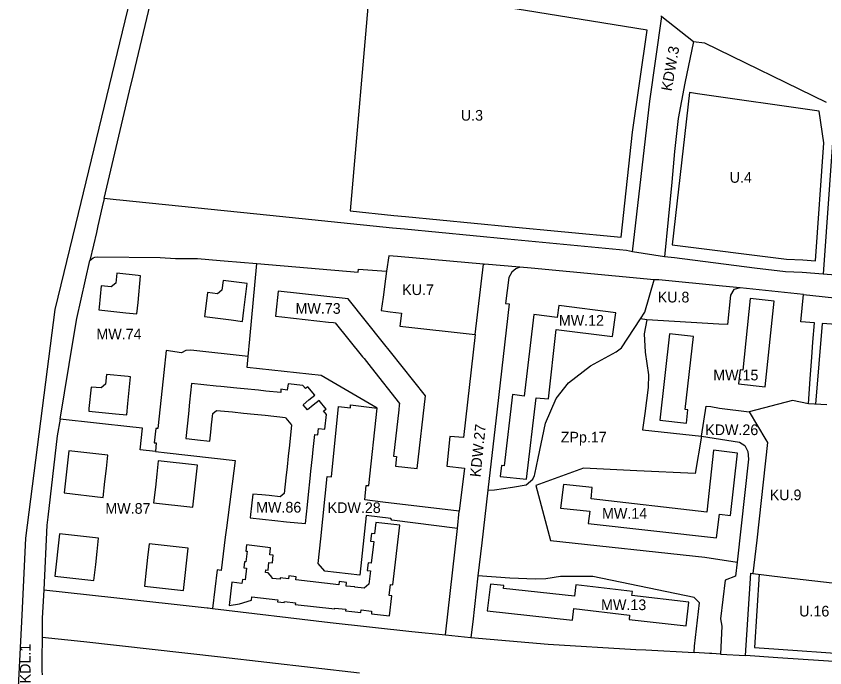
# Model space of a CAD drawing. Extents: x 7424434 to 7425898, y 5541432 to 5542659.
# Drawn here: x 7424614.7 to 7424993.9, y 5541854.6 to 5542160 of the extents above; entities that cross this region are included whole.
import ezdxf

# ---------------------------------------------------------------- set-up
doc = ezdxf.new("R2010")
doc.units = 0
for name, color, linetype in [('linie rozgraniczające', 7, 'Continuous'), ('nieprzekraczalne linie zabudowy', 7, 'Continuous'), ('obowiazujace linie zabudowy', 7, 'Continuous'), ('przeznaczenia terenów', 7, 'Continuous')]:
    doc.layers.add(name, color=color, linetype=linetype)

msp = doc.modelspace()

# ---------------------------------------------------------------- linework, layer by layer
at = {"layer": 'linie rozgraniczające'}
for p, q in [((7424665.78, 5542157.87), (7424709.76, 5542339.63)), ((7424674.48, 5542152.32), (7424683.68, 5542191.73)), ((7424911.87, 5542120.2), (7424917.55, 5542159.83)), ((7424917.08, 5542160.2), (7424917.55, 5542159.83)), ((7424917.55, 5542159.83), (7424932.4, 5542148.13)), ((7424642.66, 5542062.32), (7424665.78, 5542157.87)), ((7424669.75, 5542132.74), (7424674.48, 5542152.32)), ((7424932.4, 5542148.13), (7424928.28, 5542128.55)), ((7424932.4, 5542148.13), (7424937.56, 5542147.46)), ((7424937.56, 5542147.46), (7424994.63, 5542119.66)), ((7424667.94, 5542125.06), (7424669.75, 5542132.74)), ((7424928.28, 5542128.55), (7424925.24, 5542112.08)), ((7424656.01, 5542074.49), (7424667.94, 5542125.06)), ((7424903.7, 5542049.58), (7424911.87, 5542120.2)), ((7424925.24, 5542112.08), (7424923.48, 5542096.58)), ((7424997.54, 5542100.77), (7424993.13, 5542039.11)), ((7424923.48, 5542096.58), (7424922.23, 5542082.23)), ((7424922.23, 5542082.23), (7424918.72, 5542047.27)), ((7424656.01, 5542074.49), (7424655.09, 5542070.61)), ((7424661.58, 5542073.91), (7424656.01, 5542074.49)), ((7424661.62, 5542073.91), (7424661.58, 5542073.91)), ((7424663.37, 5542073.73), (7424661.62, 5542073.91)), ((7424733.65, 5542066.56), (7424663.37, 5542073.73)), ((7424655.09, 5542070.61), (7424653.05, 5542061.69)), ((7424791.18, 5542060.69), (7424733.65, 5542066.56)), ((7424633.04, 5542022.53), (7424642.66, 5542062.32)), ((7424653.05, 5542061.69), (7424652.36, 5542058.67)), ((7424652.36, 5542058.67), (7424650.99, 5542052.64)), ((7424796.79, 5542060.12), (7424791.18, 5542060.69)), ((7424845.09, 5542055.47), (7424796.79, 5542060.12)), ((7424901.01, 5542050.11), (7424845.09, 5542055.47)), ((7424650.99, 5542052.64), (7424649.32, 5542045.47)), ((7424903.7, 5542049.58), (7424901.01, 5542050.11)), ((7424918.72, 5542047.27), (7424903.7, 5542049.58)), ((7424649.32, 5542045.47), (7424650.81, 5542046.77)), ((7424650.81, 5542046.77), (7424651.6, 5542047.07)), ((7424651.6, 5542047.07), (7424653.06, 5542047.28)), ((7424653.06, 5542047.28), (7424682.27, 5542046.94)), ((7424682.27, 5542046.94), (7424689.5, 5542046.5)), ((7424689.5, 5542046.5), (7424697.61, 5542046.41)), ((7424697.61, 5542046.41), (7424699.77, 5542046.44)), ((7424699.77, 5542046.44), (7424710.35, 5542045.47)), ((7424789.43, 5542047.72), (7424788.46, 5542040.46)), ((7424793.49, 5542047.36), (7424789.43, 5542047.72)), ((7424833.85, 5542043.8), (7424793.49, 5542047.36)), ((7424923.5, 5542046.67), (7424918.72, 5542047.27)), ((7424961.02, 5542041.95), (7424923.5, 5542046.67)), ((7424643.14, 5542018.33), (7424649.32, 5542045.47)), ((7424710.35, 5542045.47), (7424712.29, 5542045.35)), ((7424712.29, 5542045.35), (7424727.53, 5542044.01)), ((7424724.3, 5542008.68), (7424727.53, 5542044.01)), ((7424727.53, 5542044.01), (7424775.07, 5542039.96)), ((7424830.04, 5542010.78), (7424833.85, 5542043.8)), ((7424833.85, 5542043.8), (7424834.39, 5542043.75)), ((7424850.93, 5542042.31), (7424834.39, 5542043.75)), ((7424850.93, 5542042.31), (7424849.03, 5542041.57)), ((7424856.18, 5542041.89), (7424850.93, 5542042.31)), ((7424975.49, 5542040.15), (7424961.02, 5542041.95)), ((7424775.07, 5542039.96), (7424775.24, 5542041.46)), ((7424775.24, 5542041.46), (7424788.46, 5542040.46)), ((7424788.46, 5542040.46), (7424787.97, 5542036.88)), ((7424847.12, 5542040.01), (7424845.69, 5542037.54)), ((7424849.03, 5542041.57), (7424847.12, 5542040.01)), ((7424913.95, 5542036.5), (7424856.18, 5542041.89)), ((7424983.28, 5542039.88), (7424975.49, 5542040.15)), ((7424993.13, 5542039.11), (7424983.28, 5542039.88)), ((7425012.26, 5542037.62), (7424993.13, 5542039.11)), ((7424787.97, 5542036.88), (7424786.83, 5542028.37)), ((7424845.69, 5542037.54), (7424844.24, 5542025.38)), ((7424909.5, 5542021.32), (7424913.95, 5542036.5)), ((7424916.07, 5542036.36), (7424913.95, 5542036.5)), ((7424945.93, 5542033.43), (7424916.07, 5542036.36)), ((7424954.19, 5542032.62), (7424945.93, 5542033.43)), ((7424951.24, 5542031.86), (7424949.75, 5542029.28)), ((7424954.19, 5542032.62), (7424951.24, 5542031.86)), ((7424984.02, 5542029.59), (7424954.19, 5542032.62)), ((7424786.83, 5542028.37), (7424785.95, 5542022.03)), ((7424949.75, 5542029.28), (7424948.38, 5542015.44)), ((7424982.62, 5542016.75), (7424984.02, 5542029.59)), ((7424984.02, 5542029.59), (7425010.84, 5542026.55)), ((7424845.92, 5542025.19), (7424840.27, 5541975.86)), ((7424844.24, 5542025.38), (7424845.92, 5542025.19)), ((7424628.68, 5541988.49), (7424633.04, 5542022.53)), ((7424785.95, 5542022.03), (7424790.07, 5542021.46)), ((7424790.07, 5542021.46), (7424795.4, 5542020.77)), ((7424795.4, 5542020.77), (7424794.71, 5542014.7)), ((7424907.57, 5542018.17), (7424909.5, 5542021.32)), ((7424641.62, 5542009.11), (7424643.14, 5542018.33)), ((7424898.57, 5542004.58), (7424907.57, 5542018.17)), ((7424910.51, 5542017.75), (7424907.57, 5542018.17)), ((7424910.51, 5542017.75), (7424909.3, 5542011.06)), ((7424944.31, 5542015.69), (7424910.51, 5542017.75)), ((7424948.38, 5542015.44), (7424944.31, 5542015.69)), ((7424989.06, 5542016.28), (7424982.62, 5542016.75)), ((7424988.4, 5542007.18), (7424989.06, 5542016.28)), ((7424794.71, 5542014.7), (7424830.04, 5542010.78)), ((7424635.31, 5541971.16), (7424641.62, 5542009.11)), ((7424723.55, 5542000.52), (7424724.3, 5542008.68)), ((7424830.04, 5542010.78), (7424824.47, 5541962.45)), ((7424909.3, 5542011.06), (7424909.68, 5542002.55)), ((7424896.15, 5542002.69), (7424898.57, 5542004.58)), ((7424987.89, 5542000.14), (7424988.4, 5542007.18)), ((7424685.01, 5542003.34), (7424683.95, 5541993.04)), ((7424692.24, 5542002.21), (7424685.01, 5542003.34)), ((7424694.31, 5542003.28), (7424692.24, 5542002.21)), ((7424696.64, 5542003.45), (7424694.31, 5542003.28)), ((7424723.55, 5542000.52), (7424696.64, 5542003.45)), ((7424723.07, 5541995.34), (7424723.55, 5542000.52)), ((7424884.08, 5541996.04), (7424896.15, 5542002.69)), ((7424909.68, 5542002.55), (7424911.22, 5541991.96)), ((7424987.15, 5541989.97), (7424987.89, 5542000.14)), ((7424683.95, 5541993.04), (7424681.32, 5541968.12)), ((7424757.8, 5541991.59), (7424723.07, 5541995.34)), ((7424873.7, 5541988.1), (7424884.08, 5541996.04)), ((7424783.97, 5541976.29), (7424757.8, 5541991.59)), ((7424911.22, 5541991.96), (7424911.08, 5541985.97)), ((7424986.31, 5541978.38), (7424987.15, 5541989.97)), ((7424619.31, 5541915.32), (7424628.68, 5541988.49)), ((7424867.96, 5541980.76), (7424873.7, 5541988.1)), ((7424911.08, 5541985.97), (7424909.51, 5541973.82)), ((7424771.47, 5541976.44), (7424771.47, 5541977.76)), ((7424771.47, 5541977.76), (7424783.97, 5541976.29)), ((7424862.91, 5541969.18), (7424867.96, 5541980.76)), ((7424978.75, 5541979.87), (7424958.39, 5541974.57)), ((7424986.31, 5541978.38), (7424978.75, 5541979.87)), ((7424994.88, 5541977.76), (7424986.31, 5541978.38)), ((7424762.64, 5541944.03), (7424765.96, 5541977.08)), ((7424765.96, 5541977.08), (7424771.47, 5541976.44)), ((7424780.17, 5541939.96), (7424783.97, 5541976.29)), ((7424840.27, 5541975.86), (7424835.91, 5541937.86)), ((7424909.51, 5541973.82), (7424908.45, 5541966.05)), ((7424936.04, 5541963.13), (7424938.31, 5541977.21)), ((7424938.31, 5541977.21), (7424940.42, 5541976.99)), ((7424940.42, 5541976.99), (7424944.5, 5541976.28)), ((7424944.5, 5541976.28), (7424958.39, 5541974.57)), ((7424958.39, 5541974.57), (7424966.33, 5541961.43)), ((7424635.31, 5541971.16), (7424634.01, 5541963.32)), ((7424669.39, 5541967.34), (7424635.31, 5541971.16)), ((7424673.94, 5541966.83), (7424669.39, 5541967.34)), ((7424672.81, 5541956.81), (7424673.94, 5541966.83)), ((7424680.16, 5541966.77), (7424679.48, 5541960.05)), ((7424681.16, 5541966.67), (7424680.16, 5541966.77)), ((7424681.32, 5541968.12), (7424681.16, 5541966.67)), ((7424859.48, 5541952.89), (7424862.91, 5541969.18)), ((7424634.01, 5541963.32), (7424629.57, 5541925.13)), ((7424818.16, 5541962.95), (7424816.62, 5541949.09)), ((7424824.47, 5541962.45), (7424818.16, 5541962.95)), ((7424908.45, 5541966.05), (7424936.04, 5541963.13)), ((7424936.04, 5541963.13), (7424933.21, 5541945.59)), ((7424936.04, 5541963.13), (7424953.94, 5541960.31)), ((7424679.48, 5541960.05), (7424680.45, 5541959.95)), ((7424680.45, 5541959.95), (7424680.04, 5541956)), ((7424953.94, 5541960.31), (7424956.43, 5541958.72)), ((7424956.43, 5541958.72), (7424957.81, 5541955.96)), ((7424967.12, 5541960.12), (7424962, 5541914.34)), ((7424966.33, 5541961.43), (7424967.12, 5541960.12)), ((7424680.04, 5541956), (7424672.81, 5541956.81)), ((7424680.04, 5541956), (7424685.53, 5541955.38)), ((7424685.53, 5541955.38), (7424717.41, 5541951.8)), ((7424957.81, 5541955.96), (7424958.21, 5541952.41)), ((7424717.41, 5541951.8), (7424713.31, 5541920.22)), ((7424858.03, 5541945.39), (7424859.48, 5541952.89)), ((7424958.21, 5541952.41), (7424952.8, 5541904.1)), ((7424816.62, 5541949.09), (7424824.97, 5541948.08)), ((7424824.97, 5541948.08), (7424822.54, 5541927.92)), ((7424880.76, 5541948.22), (7424858.5, 5541940.1)), ((7424905.85, 5541946.96), (7424880.76, 5541948.22)), ((7424757.57, 5541915.06), (7424760.54, 5541944.28)), ((7424760.54, 5541944.28), (7424762.64, 5541944.03)), ((7424856.96, 5541942.92), (7424857.77, 5541944.67)), ((7424857.77, 5541944.67), (7424858.03, 5541945.39)), ((7424933.21, 5541945.59), (7424905.85, 5541946.96)), ((7424778.17, 5541933.24), (7424778.9, 5541940.1)), ((7424778.9, 5541940.1), (7424780.17, 5541939.96)), ((7424847.55, 5541939.24), (7424853.88, 5541940.34)), ((7424853.88, 5541940.34), (7424856.96, 5541942.92)), ((7424858.5, 5541940.1), (7424858.48, 5541940.09)), ((7424858.48, 5541940.09), (7424865.37, 5541914.28)), ((7424835.91, 5541937.86), (7424833.07, 5541913.13)), ((7424835.91, 5541937.86), (7424839.1, 5541937.97)), ((7424839.1, 5541937.97), (7424847.55, 5541939.24)), ((7424786.65, 5541932.2), (7424778.17, 5541933.24)), ((7424822.54, 5541927.92), (7424786.65, 5541932.2)), ((7424629.57, 5541925.13), (7424629.15, 5541921.5)), ((7424778.81, 5541926), (7424775.85, 5541897.95)), ((7424790.43, 5541924.63), (7424778.81, 5541926)), ((7424790.97, 5541923.7), (7424790.43, 5541924.63)), ((7424821.7, 5541919.91), (7424822.54, 5541927.92)), ((7424629.15, 5541921.5), (7424627.65, 5541891.08)), ((7424821.7, 5541919.91), (7424790.97, 5541923.7)), ((7424713.31, 5541920.22), (7424712.78, 5541915.87)), ((7424815.99, 5541869.99), (7424821.7, 5541919.91)), ((7424617.47, 5541879.28), (7424619.31, 5541915.32)), ((7424712.78, 5541915.87), (7424710.9, 5541900.22)), ((7424756.29, 5541903.48), (7424757.57, 5541915.06)), ((7424833.07, 5541913.13), (7424831.3, 5541897.67)), ((7424865.37, 5541914.28), (7424937.63, 5541906.36)), ((7424962, 5541914.34), (7424960.25, 5541898.76)), ((7424937.63, 5541906.36), (7424952.8, 5541904.1)), ((7424759.43, 5541899.8), (7424756.29, 5541903.48)), ((7424952.8, 5541904.1), (7424952.09, 5541897.53)), ((7424708.96, 5541900.44), (7424706.75, 5541882.43)), ((7424710.9, 5541900.22), (7424708.96, 5541900.44)), ((7424775.85, 5541897.95), (7424759.43, 5541899.8)), ((7424956.76, 5541860.36), (7424959.23, 5541898.88)), ((7424959.23, 5541898.88), (7424960.25, 5541898.76)), ((7424960.25, 5541898.76), (7424974.32, 5541897.1)), ((7424831.3, 5541897.67), (7424828.82, 5541876.04)), ((7424846.18, 5541896.61), (7424831.3, 5541897.67)), ((7424858.31, 5541896.08), (7424846.18, 5541896.61)), ((7424863.08, 5541896.21), (7424858.31, 5541896.08)), ((7424870.01, 5541897.38), (7424863.08, 5541896.21)), ((7424885.22, 5541897.4), (7424870.01, 5541897.38)), ((7424932.75, 5541887.46), (7424885.22, 5541897.4)), ((7424947.18, 5541895.66), (7424945.08, 5541877.55)), ((7424952.09, 5541897.53), (7424947.18, 5541895.66)), ((7424974.32, 5541897.1), (7425005.9, 5541893.39)), ((7424627.65, 5541891.08), (7424627, 5541877.79)), ((7424627.65, 5541891.08), (7424660.5, 5541887.5)), ((7424660.5, 5541887.5), (7424660.52, 5541887.5)), ((7424660.52, 5541887.5), (7424704.32, 5541882.72)), ((7424935.19, 5541885.05), (7424932.75, 5541887.46)), ((7424704.32, 5541882.72), (7424704.79, 5541882.66)), ((7424704.79, 5541882.66), (7424705.7, 5541882.56)), ((7424932.86, 5541864.65), (7424935.19, 5541885.05)), ((7424614.73, 5541825.47), (7424617.47, 5541879.28)), ((7424705.7, 5541882.56), (7424706.75, 5541882.43)), ((7424706.75, 5541882.43), (7424761.91, 5541875.76)), ((7424627, 5541877.79), (7424626.91, 5541868.82)), ((7424761.91, 5541875.76), (7424800.28, 5541871.66)), ((7424828.82, 5541876.04), (7424827.98, 5541868.72)), ((7424945.08, 5541877.55), (7424945.7, 5541874.11)), ((7424800.28, 5541871.66), (7424815.99, 5541869.99)), ((7424945.7, 5541874.11), (7424945.09, 5541861)), ((7424626.91, 5541868.82), (7424626.71, 5541858.72)), ((7424646.44, 5541866.67), (7424626.91, 5541868.82)), ((7424815.99, 5541869.99), (7424827.98, 5541868.72)), ((7424827.98, 5541868.72), (7424864.18, 5541865.6)), ((7424710.49, 5541859.62), (7424646.44, 5541866.67)), ((7424864.18, 5541865.6), (7424905.36, 5541863.18)), ((7424932.65, 5541861.68), (7424932.86, 5541864.65)), ((7424905.36, 5541863.18), (7424910.07, 5541862.92)), ((7424910.07, 5541862.92), (7424932.65, 5541861.68)), ((7424939.88, 5541861.28), (7424932.65, 5541861.68)), ((7424941.01, 5541861.22), (7424939.88, 5541861.28)), ((7424945.09, 5541861), (7424941.01, 5541861.22)), ((7424945.09, 5541861), (7424956.76, 5541860.36)), ((7424971.91, 5541859.31), (7424956.76, 5541860.36)), ((7424626.71, 5541858.72), (7424626.92, 5541838.97)), ((7424775.7, 5541852), (7424710.49, 5541859.62)), ((7425003.17, 5541857.12), (7424971.91, 5541859.31))]:
    msp.add_line(p, q, dxfattribs=at)
at = {"layer": 'nieprzekraczalne linie zabudowy'}
for points in [[(7424910.57, 5542153.41), (7424853.59, 5542162.67), (7424838.77, 5542165.08), (7424780.57, 5542175.11), (7424771.38, 5542068.74), (7424791.79, 5542066.66), (7424797.38, 5542066.09), (7424845.66, 5542061.44), (7424898.44, 5542056.38), (7424903.72, 5542105.59)], [(7424993.52, 5542100.61), (7424991.23, 5542115.49), (7424934.27, 5542123.65), (7424930.52, 5542124.18), (7424922.3, 5542052.87), (7424922.3, 5542052.87), (7424922.3, 5542052.87), (7424975.97, 5542046.14), (7424983.62, 5542045.87), (7424989.57, 5542045.41)]]:
    msp.add_lwpolyline(points, close=True, dxfattribs=at)
for points in [[(7425039.61, 5542012.61), (7425034.97, 5542012.95), (7424992.66, 5542016.02), (7424989.51, 5541978.15)], [(7424963.21, 5541898.41), (7424961.01, 5541864.08), (7424972.19, 5541863.3), (7425003.4, 5541861.11)]]:
    msp.add_lwpolyline(points, dxfattribs=at)
at = {"layer": 'obowiazujace linie zabudowy'}
for points in [[(7424661.93, 5542039.52), (7424661.42, 5542034.85), (7424659.3, 5542033.13), (7424654.65, 5542033.57), (7424653.63, 5542023.55), (7424653.53, 5542022.39), (7424666.08, 5542021.03), (7424671.36, 5542020.54), (7424671.91, 5542025.85), (7424672.96, 5542038.34), (7424672, 5542038.47)], [(7424711.79, 5542036.18), (7424711.21, 5542031.52), (7424709.15, 5542029.82), (7424704.45, 5542030.44), (7424703.22, 5542020.4), (7424703.08, 5542019.21), (7424715.56, 5542017.62), (7424720.89, 5542016.94), (7424721.5, 5542022.23), (7424723.07, 5542034.68), (7424721.88, 5542034.85)], [(7424790.28, 5542002.63), (7424786.95, 5542006.81), (7424770.48, 5542027.49), (7424737.62, 5542031.11), (7424736.49, 5542020.86), (7424736.32, 5542019.36), (7424739.31, 5542019.03), (7424761.22, 5542016.61), (7424763.52, 5542016.36), (7424764.31, 5542016.28), (7424777.19, 5542000.4), (7424777.88, 5541999.54), (7424781.2, 5541995.37), (7424794.45, 5541978.46), (7424794.36, 5541977.69), (7424794.11, 5541975.43), (7424791.64, 5541953.82), (7424793.1, 5541953.66), (7424792.58, 5541949.16), (7424802.81, 5541947.99), (7424806.73, 5541981.98)], [(7424958.97, 5542027.72), (7424955.46, 5541994.13), (7424954.18, 5541994.26), (7424953.44, 5541987.74), (7424966.02, 5541986.28), (7424970.19, 5542026.48)], [(7424895.89, 5542021), (7424869.17, 5542024.45), (7424868.44, 5542018.79), (7424857.46, 5542020.21), (7424852.94, 5541981.97), (7424847.5, 5541982.62), (7424843.55, 5541949.18), (7424842.27, 5541949.33), (7424841.68, 5541944.3), (7424853.98, 5541942.97), (7424858.55, 5541981.07), (7424864.33, 5541980.71), (7424868.02, 5542013.11), (7424894.43, 5542009.89)], [(7424916.63, 5541970.62), (7424929.11, 5541969.3), (7424929.7, 5541975.47), (7424928.53, 5541975.62), (7424932.29, 5542009.94), (7424921.09, 5542011.18)], [(7424657.14, 5541992.09), (7424656.65, 5541987.46), (7424654.52, 5541985.74), (7424649.88, 5541986.18), (7424648.86, 5541976.16), (7424648.73, 5541974.9), (7424661.31, 5541973.64), (7424666.55, 5541973.14), (7424667.11, 5541978.45), (7424668.3, 5541991), (7424667.18, 5541991.11)], [(7424749.24, 5541977.88), (7424752.03, 5541980.11), (7424754.81, 5541982.34), (7424751.5, 5541986.35), (7424750.42, 5541985.45), (7424749.17, 5541986.96), (7424742.24, 5541987.66), (7424741.89, 5541984.72), (7424738.9, 5541985.11), (7424738.77, 5541983.6), (7424738.77, 5541983.6), (7424731.82, 5541984.28), (7424728.3, 5541984.65), (7424721.68, 5541985.35), (7424718.17, 5541985.71), (7424710.68, 5541986.45), (7424708.52, 5541986.66), (7424697.01, 5541987.86), (7424696.04, 5541979.04), (7424695.48, 5541973.59), (7424694.31, 5541962.03), (7424695.82, 5541961.87), (7424699.76, 5541961.45), (7424705.55, 5541960.81), (7424706.03, 5541964.97), (7424706.38, 5541968.5), (7424706.91, 5541973.72), (7424708.74, 5541975.22), (7424716.22, 5541974.48), (7424721.31, 5541973.96), (7424726.34, 5541973.46), (7424731.45, 5541972.92), (7424740.98, 5541971.91), (7424741.25, 5541971.65), (7424743.55, 5541968.8), (7424743.83, 5541968.52), (7424742.87, 5541958.93), (7424742.32, 5541953.81), (7424741.78, 5541948.8), (7424741.26, 5541943.65), (7424740.47, 5541936.33), (7424738.6, 5541934.73), (7424733.37, 5541935.27), (7424729.86, 5541935.63), (7424725.69, 5541936.03), (7424725.04, 5541930.42), (7424724.65, 5541926.47), (7424724.48, 5541924.83), (7424736.08, 5541923.63), (7424741.53, 5541923.06), (7424750.39, 5541922.15), (7424751.29, 5541930.99), (7424751.81, 5541935.87), (7424752.63, 5541943.29), (7424752.99, 5541946.81), (7424753.66, 5541953.47), (7424754.04, 5541956.93), (7424754.73, 5541963.92), (7424756.22, 5541963.74), (7424756.53, 5541966.74), (7424759.49, 5541966.42), (7424760.25, 5541973.35), (7424758.92, 5541974.99), (7424760.05, 5541975.88), (7424756.82, 5541979.82), (7424754.05, 5541977.62), (7424751.34, 5541975.46)], [(7424639.39, 5541956.28), (7424637.19, 5541936.51), (7424655.52, 5541934.46), (7424656.35, 5541941.93), (7424657.09, 5541947.92), (7424657.72, 5541954.25)], [(7424870.02, 5541929.39), (7424883.68, 5541927.93), (7424883.02, 5541922.19), (7424943.14, 5541915.49), (7424944.56, 5541926.56), (7424949.73, 5541925.97), (7424953.07, 5541955.13), (7424941.68, 5541956.54), (7424938.58, 5541927.52), (7424884.3, 5541933.72), (7424884.87, 5541939.05), (7424871.33, 5541940.5)], [(7424681.38, 5541951.61), (7424680.67, 5541945.32), (7424680, 5541939.27), (7424679.17, 5541931.83), (7424697.51, 5541929.79), (7424699.71, 5541949.56)], [(7424773.52, 5541892.44), (7424773.52, 5541892.45), (7424769.48, 5541892.91), (7424769.67, 5541894.58), (7424766.17, 5541894.98), (7424766, 5541893.51), (7424745.88, 5541895.79), (7424746.05, 5541897.24), (7424742.56, 5541897.63), (7424742.41, 5541896.32), (7424738.57, 5541896.75), (7424738.49, 5541896.04), (7424734.76, 5541896.47), (7424734.81, 5541896.97), (7424732.93, 5541899.15), (7424731.68, 5541899.29), (7424731.82, 5541900.52), (7424732.85, 5541900.41), (7424733.25, 5541903.94), (7424734.86, 5541903.76), (7424735.27, 5541907.33), (7424733.67, 5541907.51), (7424734.06, 5541910.87), (7424722.8, 5541912.16), (7424722.47, 5541909.3), (7424723, 5541909.24), (7424722.42, 5541904.24), (7424721.85, 5541904.3), (7424721.52, 5541901.42), (7424722.74, 5541901.28), (7424722.12, 5541895.85), (7424720.81, 5541896), (7424720.6, 5541894.14), (7424715.9, 5541894.68), (7424714.65, 5541883.76), (7424719.44, 5541884.48), (7424725.02, 5541886.25), (7424725.19, 5541887.81), (7424737.37, 5541886.47), (7424737.26, 5541885.48), (7424740.48, 5541885.13), (7424740.54, 5541885.65), (7424745.71, 5541885.09), (7424745.62, 5541884.28), (7424764.18, 5541882.25), (7424764.22, 5541882.57), (7424769.26, 5541882.02), (7424769.18, 5541881.29), (7424772.21, 5541880.94), (7424776.31, 5541880.46), (7424776.45, 5541881.71), (7424781.43, 5541881.13), (7424781.29, 5541879.89), (7424789.73, 5541878.89), (7424790.83, 5541888.28), (7424789.64, 5541888.42), (7424790.25, 5541893.62), (7424791.44, 5541893.48), (7424794.71, 5541921.39), (7424783.46, 5541922.71), (7424782.84, 5541917.35), (7424781.35, 5541917.52), (7424780.94, 5541913.94), (7424782.43, 5541913.77), (7424781.26, 5541903.64), (7424779.77, 5541903.81), (7424779.36, 5541900.23), (7424780.85, 5541900.06), (7424780.12, 5541893.74), (7424777.91, 5541891.89)], [(7424635.05, 5541917.33), (7424632.85, 5541897.54), (7424651.19, 5541895.51), (7424652.02, 5541902.92), (7424652.79, 5541909.02), (7424653.39, 5541915.28)], [(7424677.04, 5541912.66), (7424676.31, 5541906.3), (7424675.66, 5541900.29), (7424674.84, 5541892.87), (7424693.17, 5541890.83), (7424695.37, 5541910.61)], [(7424928.9, 5541874.21), (7424930.2, 5541885.38), (7424903.48, 5541888.49), (7424903.69, 5541890.34), (7424877.26, 5541893.39), (7424876.51, 5541888.08), (7424843.33, 5541891.74), (7424843.46, 5541893.08), (7424837.09, 5541893.71), (7424835.64, 5541881.28), (7424875.57, 5541876.88), (7424876.22, 5541882.34), (7424902.35, 5541879.26), (7424902.12, 5541877.27)]]:
    msp.add_lwpolyline(points, close=True, dxfattribs=at)

# ---------------------------------------------------------------- texts
at = {"layer": 'przeznaczenia terenów'}
for s, rotation, p in [('KDW.3', 80, (7424922.07, 5542124.63)), ('KDW.27', 84, (7424832.43, 5541943.76)), ('KDL.1', 90, (7424621.48, 5541847.26))]:
    msp.add_text(s, height=5, rotation=rotation, dxfattribs=at).set_placement(p)
for s, p in [('U.3', (7424823.27, 5542111.05)), ('U.4', (7424949.32, 5542081.93)), ('KU.7', (7424795.76, 5542029.3)), ('KU.8', (7424915.57, 5542025.82)), ('MW.73', (7424745.73, 5542020.5)), ('MW.12', (7424869.21, 5542014.93)), ('MW.74', (7424652.36, 5542008.51)), ('MW.15', (7424941.62, 5541989.29)), ('KDW.26', (7424937.84, 5541963.64)), ('ZPp.17', (7424870.1, 5541960.18)), ('KU.9', (7424968.12, 5541933.13)), ('MW.86', (7424727.26, 5541927.35)), ('KDW.28', (7424760.8, 5541927.12)), ('MW.87', (7424656.55, 5541926.77)), ('MW.14', (7424889.46, 5541924.44)), ('MW.13', (7424889.02, 5541881.6)), ('U.16', (7424981.92, 5541878.63))]:
    msp.add_text(s, height=5, dxfattribs=at).set_placement(p)

doc.saveas('drawing.dxf')
